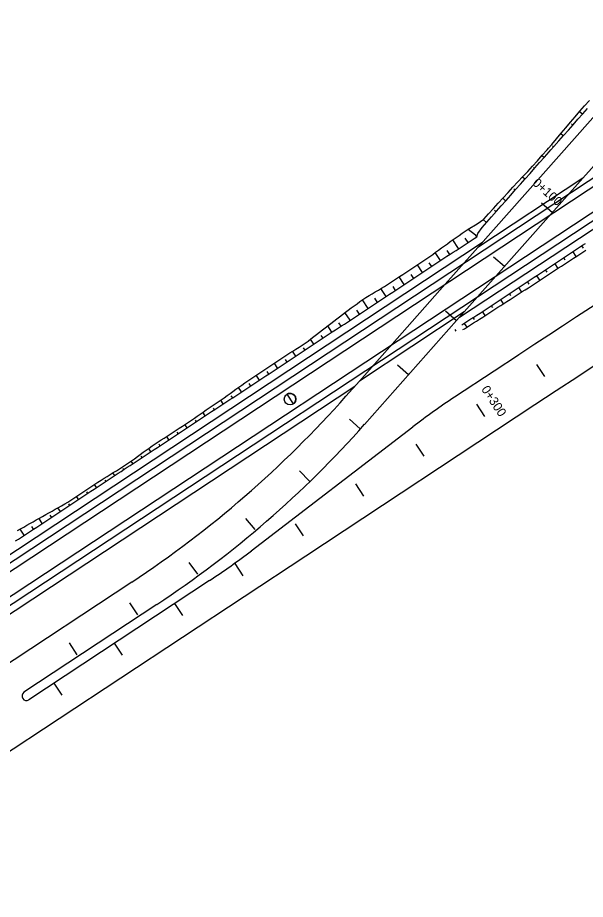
# Model space of a CAD drawing. Extents: x 6503541 to 6503743, y 5888004 to 5888145.
# Drawn here: x 6503598.537 to 6503600.423, y 5888050.855 to 5888053.781 of the extents above; entities that cross this region are included whole.
import ezdxf

# ---------------------------------------------------------------- set-up
doc = ezdxf.new("R2010")
doc.units = 0
doc.layers.add('12', color=7, linetype='Continuous')

msp = doc.modelspace()

# ---------------------------------------------------------------- linework, layer by layer
at = {"layer": '12'}
for p, q in [((6503592.6202, 5888048.0879), (6503601.3481, 5888053.842)), ((6503592.6334, 5888048.0679), (6503601.3614, 5888053.822)), ((6503592.6717, 5888048.0098), (6503601.3997, 5888053.7639)), ((6503592.6849, 5888047.9897), (6503601.4129, 5888053.7438)), ((6503600.0053, 5888052.7871), (6503601.4261, 5888053.7238)), ((6503600.6305, 5888053.6545), (6503600.0661, 5888053.0184)), ((6503600.414, 5888053.2477), (6503600.6975, 5888053.5672)), ((6503600.0206, 5888052.8044), (6503600.414, 5888053.2477)), ((6503600.0206, 5888052.8044), (6503600.414, 5888053.2477)), ((6503600.414, 5888053.2477), (6503600.0661, 5888053.0184)), ((6503600.414, 5888053.2477), (6503600.0661, 5888053.0184)), ((6503600.0621, 5888053.0539), (6503600.0584, 5888053.0602)), ((6503596.6916, 5888050.8008), (6503600.0814, 5888053.0357)), ((6503600.0019, 5888053.0143), (6503599.9827, 5888053.0435)), ((6503600.0221, 5888053.0492), (6503600.032, 5888053.0341)), ((6503599.9418, 5888052.9747), (6503599.9242, 5888053.0013)), ((6503599.9399, 5888052.8761), (6503600.0661, 5888053.0184)), ((6503599.9399, 5888052.8761), (6503600.0661, 5888053.0184)), ((6503599.9627, 5888053.0085), (6503599.9719, 5888052.9945)), ((6503600.381, 5888053.0038), (6503600.3915, 5888052.9879)), ((6503600.4163, 5888053.0156), (6503600.4111, 5888053.0236)), ((6503600.3562, 5888052.976), (6503600.351, 5888052.984)), ((6503599.8817, 5888052.935), (6503599.865, 5888052.9604)), ((6503599.9034, 5888052.9675), (6503599.9118, 5888052.9548)), ((6503600.296, 5888052.9365), (6503600.2909, 5888052.9443)), ((6503600.3209, 5888052.9641), (6503600.3313, 5888052.9484)), ((6503599.8216, 5888052.8954), (6503599.8047, 5888052.921)), ((6503599.8433, 5888052.928), (6503599.8517, 5888052.9152)), ((6503600.2608, 5888052.9245), (6503600.2711, 5888052.9089)), ((6503599.7831, 5888052.8884), (6503599.7915, 5888052.8756)), ((6503600.2007, 5888052.8849), (6503600.2105, 5888052.87)), ((6503600.2359, 5888052.8969), (6503600.2307, 5888052.9047)), ((6503599.6727, 5888052.5751), (6503599.9399, 5888052.8761)), ((6503599.6727, 5888052.5751), (6503599.9399, 5888052.8761)), ((6503599.7615, 5888052.8558), (6503599.7441, 5888052.8821)), ((6503600.1754, 5888052.8578), (6503600.1706, 5888052.8651)), ((6503599.7014, 5888052.8161), (6503599.6827, 5888052.8445)), ((6503599.7223, 5888052.8498), (6503599.7314, 5888052.8359)), ((6503600.1151, 5888052.8185), (6503600.1105, 5888052.8254)), ((6503600.1406, 5888052.8453), (6503600.15, 5888052.831)), ((6503599.6413, 5888052.7765), (6503599.6244, 5888052.8022)), ((6503599.6623, 5888052.8099), (6503599.6713, 5888052.7963)), ((6503600.0206, 5888052.8044), (6503599.6727, 5888052.5751)), ((6503600.0206, 5888052.8044), (6503599.6727, 5888052.5751)), ((6503599.6896, 5888052.4313), (6503600.0206, 5888052.8044)), ((6503600.0805, 5888052.8056), (6503600.0894, 5888052.792)), ((6503599.6035, 5888052.7684), (6503599.6112, 5888052.7567)), ((6503600.0203, 5888052.766), (6503600.0287, 5888052.7534)), ((6503600.0548, 5888052.7792), (6503600.0504, 5888052.7858)), ((6503599.5812, 5888052.7369), (6503599.5672, 5888052.7581)), ((6503599.994, 5888052.7405), (6503599.9903, 5888052.7462)), ((6503599.521, 5888052.6972), (6503599.51, 5888052.714)), ((6503599.5448, 5888052.7265), (6503599.5511, 5888052.7171)), ((6503599.4857, 5888052.6854), (6503599.491, 5888052.6774)), ((6503599.4609, 5888052.6576), (6503599.4504, 5888052.6736)), ((6503600.2004, 5888052.6611), (6503600.1195, 5888052.6078)), ((6503599.4008, 5888052.618), (6503599.3901, 5888052.6342)), ((6503599.4256, 5888052.6459), (6503599.4309, 5888052.6378)), ((6503599.3407, 5888052.5784), (6503599.3301, 5888052.5945)), ((6503599.3654, 5888052.6063), (6503599.3708, 5888052.5982)), ((6503600.1195, 5888052.6078), (6503599.9886, 5888052.5215)), ((6503599.3054, 5888052.5665), (6503599.3107, 5888052.5585)), ((6503599.6277, 5888052.5243), (6503599.6727, 5888052.5751)), ((6503596.8173, 5888050.6854), (6503599.6574, 5888052.5577)), ((6503599.2806, 5888052.5387), (6503599.2708, 5888052.5536)), ((6503599.2205, 5888052.4991), (6503599.212, 5888052.512)), ((6503599.246, 5888052.5258), (6503599.2505, 5888052.5189)), ((6503599.1864, 5888052.4854), (6503599.1904, 5888052.4793)), ((6503600.2545, 5888052.4955), (6503599.494, 5888051.9942)), ((6503599.1267, 5888052.4452), (6503599.1303, 5888052.4396)), ((6503599.1604, 5888052.4595), (6503599.1527, 5888052.4712)), ((6503599.1003, 5888052.4198), (6503599.0932, 5888052.4306)), ((6503599.3135, 5888052.0118), (6503599.8499, 5888052.4228)), ((6503599.0401, 5888052.3802), (6503599.0327, 5888052.3915)), ((6503599.0666, 5888052.4055), (6503599.0702, 5888052.4)), ((6503599.0063, 5888052.3662), (6503599.0101, 5888052.3604)), ((6503598.98, 5888052.3406), (6503598.9727, 5888052.3517)), ((6503598.9199, 5888052.3009), (6503598.9145, 5888052.3092)), ((6503598.9468, 5888052.3256), (6503598.95, 5888052.3208)), ((6503598.8598, 5888052.2613), (6503598.8538, 5888052.2704)), ((6503598.8872, 5888052.2852), (6503598.8899, 5888052.2811)), ((6503598.8265, 5888052.2465), (6503598.8298, 5888052.2415)), ((6503598.7997, 5888052.2217), (6503598.7928, 5888052.2322)), ((6503598.7396, 5888052.182), (6503598.7327, 5888052.1925)), ((6503598.7662, 5888052.2071), (6503598.7696, 5888052.2019)), ((6503598.6795, 5888052.1424), (6503598.6713, 5888052.1547)), ((6503598.7061, 5888052.1675), (6503598.7095, 5888052.1622)), ((6503598.6447, 5888052.1298), (6503598.6494, 5888052.1226)), ((6503598.6194, 5888052.1028), (6503598.6085, 5888052.1193)), ((6503598.5593, 5888052.0632), (6503598.5456, 5888052.0839)), ((6503598.5832, 5888052.0923), (6503598.5893, 5888052.083)), ((6503599.4945, 5888051.9945), (6503597.9384, 5888050.9686)), ((6503598.9165, 5888051.9081), (6503597.8024, 5888051.1736)), ((6503599.1748, 5888051.9131), (6503598.575, 5888051.5177)), ((6503598.9997, 5888051.8336), (6503598.5585, 5888051.5427))]:
    msp.add_line(p, q, dxfattribs=at)
for points in [[(6503600.0332, 5888053.079), (6503600.0634, 5888053.0964), (6503600.0853, 5888053.1115), (6503600.1013, 5888053.1294), (6503600.1173, 5888053.1472), (6503600.1334, 5888053.165), (6503600.1496, 5888053.1828), (6503600.1659, 5888053.2004), (6503600.1823, 5888053.2179), (6503600.1986, 5888053.2355), (6503600.215, 5888053.2531), (6503600.2314, 5888053.2706), (6503600.2477, 5888053.2882), (6503600.264, 5888053.3059), (6503600.2798, 5888053.3239), (6503600.2956, 5888053.342), (6503600.3009, 5888053.3481), (6503600.3112, 5888053.3602), (6503600.3268, 5888053.3785), (6503600.3423, 5888053.3968), (6503600.3579, 5888053.4151), (6503600.3734, 5888053.4334), (6503600.3889, 5888053.4517), (6503600.4044, 5888053.47), (6503600.4199, 5888053.4883), (6503600.436, 5888053.5062)], [(6503600.062, 5888053.0539), (6503600.0657, 5888053.0647), (6503600.0797, 5888053.0843), (6503600.0956, 5888053.1023), (6503600.1116, 5888053.1202), (6503600.1275, 5888053.1382), (6503600.1434, 5888053.1561), (6503600.1594, 5888053.1741), (6503600.1753, 5888053.192), (6503600.1912, 5888053.21), (6503600.2071, 5888053.2279), (6503600.2231, 5888053.2459), (6503600.239, 5888053.2639), (6503600.2549, 5888053.2818), (6503600.2709, 5888053.2998), (6503600.2868, 5888053.3177), (6503600.3027, 5888053.3357), (6503600.3081, 5888053.3418), (6503600.3186, 5888053.3536), (6503600.3346, 5888053.3716), (6503600.3505, 5888053.3895), (6503600.3664, 5888053.4075), (6503600.3824, 5888053.4254), (6503600.3983, 5888053.4434), (6503600.4142, 5888053.4613), (6503600.4301, 5888053.4793)], [(6503600.413, 5888053.46), (6503600.4032, 5888053.4686)], [(6503600.3811, 5888053.4241), (6503600.3767, 5888053.428)], [(6503600.3493, 5888053.3882), (6503600.3411, 5888053.3954)], [(6503600.3174, 5888053.3522), (6503600.3137, 5888053.3555)], [(6503600.2856, 5888053.3163), (6503600.2786, 5888053.3225)], [(6503600.2537, 5888053.2804), (6503600.2501, 5888053.2837)], [(6503600.2219, 5888053.2445), (6503600.2137, 5888053.2517)], [(6503600.19, 5888053.2086), (6503600.1855, 5888053.2126)], [(6503600.1581, 5888053.1727), (6503600.1483, 5888053.1814)], [(6503600.2772, 5888053.1658), (6503600.3131, 5888053.134)], [(6503600.1263, 5888053.1368), (6503600.1212, 5888053.1413)], [(6503600.0944, 5888053.1009), (6503600.0841, 5888053.1101)], [(6503598.5366, 5888052.0788), (6503598.5471, 5888052.0847), (6503598.5575, 5888052.0906), (6503598.568, 5888052.0965), (6503598.5785, 5888052.1024), (6503598.589, 5888052.1083), (6503598.5995, 5888052.1142), (6503598.6099, 5888052.1201), (6503598.6204, 5888052.126), (6503598.6309, 5888052.1319), (6503598.6414, 5888052.1378), (6503598.6518, 5888052.1438), (6503598.6623, 5888052.1497), (6503598.6728, 5888052.1556), (6503598.6833, 5888052.1615), (6503598.6938, 5888052.1674), (6503598.7041, 5888052.1736), (6503598.7141, 5888052.1802), (6503598.7241, 5888052.1868), (6503598.7341, 5888052.1934), (6503598.7441, 5888052.2), (6503598.7541, 5888052.2067), (6503598.7641, 5888052.2133), (6503598.7741, 5888052.2199), (6503598.7841, 5888052.2265), (6503598.7941, 5888052.2331), (6503598.8042, 5888052.2398), (6503598.8144, 5888052.2461), (6503598.8246, 5888052.2524), (6503598.8348, 5888052.2587), (6503598.845, 5888052.265), (6503598.8552, 5888052.2713), (6503598.8654, 5888052.2776), (6503598.8757, 5888052.2839), (6503598.8859, 5888052.2902), (6503598.8961, 5888052.2965), (6503598.9061, 5888052.3031), (6503598.9158, 5888052.3102), (6503598.9255, 5888052.3173), (6503598.9352, 5888052.3243), (6503598.9449, 5888052.3314), (6503598.9546, 5888052.3385), (6503598.9644, 5888052.3456), (6503598.9741, 5888052.3527), (6503598.9838, 5888052.3598), (6503598.9938, 5888052.3663), (6503599.0039, 5888052.3729), (6503599.0139, 5888052.3794), (6503599.024, 5888052.3859), (6503599.0341, 5888052.3924), (6503599.0442, 5888052.3989), (6503599.0543, 5888052.4054), (6503599.0643, 5888052.412), (6503599.0744, 5888052.4185), (6503599.0845, 5888052.425), (6503599.0946, 5888052.4315), (6503599.1046, 5888052.4381), (6503599.1145, 5888052.4449), (6503599.1244, 5888052.4517), (6503599.1342, 5888052.4585), (6503599.1441, 5888052.4653), (6503599.154, 5888052.4721), (6503599.1639, 5888052.4789), (6503599.1738, 5888052.4857), (6503599.1837, 5888052.4925), (6503599.1936, 5888052.4993), (6503599.2035, 5888052.5061), (6503599.2134, 5888052.5129), (6503599.2233, 5888052.5197), (6503599.2331, 5888052.5266), (6503599.2429, 5888052.5336), (6503599.2526, 5888052.5406), (6503599.2624, 5888052.5476), (6503599.2721, 5888052.5546), (6503599.2819, 5888052.5616), (6503599.2917, 5888052.5686), (6503599.3015, 5888052.5754), (6503599.3115, 5888052.5821), (6503599.3215, 5888052.5888), (6503599.3315, 5888052.5954), (6503599.3414, 5888052.6021), (6503599.3514, 5888052.6087), (6503599.3614, 5888052.6154), (6503599.3714, 5888052.622), (6503599.3815, 5888052.6286), (6503599.3915, 5888052.6351), (6503599.4015, 5888052.6417), (6503599.4116, 5888052.6483), (6503599.4216, 5888052.6548), (6503599.4317, 5888052.6614), (6503599.4417, 5888052.668), (6503599.4518, 5888052.6745), (6503599.4618, 5888052.6811), (6503599.4719, 5888052.6877), (6503599.4819, 5888052.6942), (6503599.4919, 5888052.7008), (6503599.5018, 5888052.7077), (6503599.5113, 5888052.715), (6503599.5209, 5888052.7224), (6503599.5304, 5888052.7297), (6503599.5399, 5888052.737), (6503599.5494, 5888052.7444), (6503599.559, 5888052.7517), (6503599.5685, 5888052.7591), (6503599.578, 5888052.7664), (6503599.5876, 5888052.7738), (6503599.5971, 5888052.7811), (6503599.6066, 5888052.7885), (6503599.6161, 5888052.7958), (6503599.6257, 5888052.8032), (6503599.6352, 5888052.8105), (6503599.645, 5888052.8175), (6503599.6547, 5888052.8245), (6503599.6645, 5888052.8315), (6503599.6743, 5888052.8385), (6503599.684, 5888052.8455), (6503599.694, 5888052.8521), (6503599.7043, 5888052.8583), (6503599.7146, 5888052.8645), (6503599.7249, 5888052.8706), (6503599.7353, 5888052.8768), (6503599.7456, 5888052.883), (6503599.7559, 5888052.8891), (6503599.7659, 5888052.8957), (6503599.776, 5888052.9022), (6503599.786, 5888052.9088), (6503599.7961, 5888052.9154), (6503599.8061, 5888052.9219), (6503599.8162, 5888052.9285), (6503599.8262, 5888052.9351), (6503599.8362, 5888052.9416), (6503599.8463, 5888052.9482), (6503599.8563, 5888052.9548), (6503599.8664, 5888052.9613), (6503599.8764, 5888052.9679), (6503599.8865, 5888052.9744), (6503599.8964, 5888052.9812), (6503599.9061, 5888052.9882), (6503599.9159, 5888052.9953), (6503599.9256, 5888053.0023), (6503599.9353, 5888053.0094), (6503599.9451, 5888053.0164), (6503599.9548, 5888053.0234), (6503599.9645, 5888053.0305), (6503599.9742, 5888053.0375), (6503599.9841, 5888053.0444), (6503599.9939, 5888053.0514), (6503600.0037, 5888053.0583), (6503600.0135, 5888053.0652), (6503600.0233, 5888053.0721), (6503600.0332, 5888053.079), (6503600.0584, 5888053.0602)], [(6503598.5306, 5888052.0443), (6503598.5406, 5888052.0509), (6503598.5506, 5888052.0575), (6503598.5606, 5888052.0641), (6503598.5707, 5888052.0707), (6503598.5807, 5888052.0773), (6503598.5907, 5888052.0839), (6503598.6007, 5888052.0905), (6503598.6107, 5888052.0971), (6503598.6208, 5888052.1037), (6503598.6308, 5888052.1103), (6503598.6408, 5888052.1169), (6503598.6508, 5888052.1235), (6503598.6608, 5888052.1301), (6503598.6708, 5888052.1367), (6503598.6809, 5888052.1433), (6503598.6909, 5888052.15), (6503598.7009, 5888052.1566), (6503598.7109, 5888052.1632), (6503598.7209, 5888052.1698), (6503598.731, 5888052.1764), (6503598.741, 5888052.183), (6503598.751, 5888052.1896), (6503598.761, 5888052.1962), (6503598.771, 5888052.2028), (6503598.781, 5888052.2094), (6503598.7911, 5888052.216), (6503598.8011, 5888052.2226), (6503598.8111, 5888052.2292), (6503598.8211, 5888052.2358), (6503598.8311, 5888052.2424), (6503598.8412, 5888052.249), (6503598.8512, 5888052.2556), (6503598.8612, 5888052.2622), (6503598.8712, 5888052.2688), (6503598.8812, 5888052.2754), (6503598.8913, 5888052.2821), (6503598.9013, 5888052.2887), (6503598.9113, 5888052.2953), (6503598.9213, 5888052.3019), (6503598.9313, 5888052.3085), (6503598.9413, 5888052.3151), (6503598.9514, 5888052.3217), (6503598.9614, 5888052.3283), (6503598.9714, 5888052.3349), (6503598.9814, 5888052.3415), (6503598.9914, 5888052.3481), (6503599.0015, 5888052.3547), (6503599.0115, 5888052.3613), (6503599.0215, 5888052.3679), (6503599.0315, 5888052.3745), (6503599.0415, 5888052.3811), (6503599.0516, 5888052.3877), (6503599.0616, 5888052.3943), (6503599.0716, 5888052.4009), (6503599.0816, 5888052.4075), (6503599.0916, 5888052.4142), (6503599.1016, 5888052.4208), (6503599.1117, 5888052.4274), (6503599.1217, 5888052.434), (6503599.1317, 5888052.4406), (6503599.1417, 5888052.4472), (6503599.1517, 5888052.4538), (6503599.1618, 5888052.4604), (6503599.1718, 5888052.467), (6503599.1818, 5888052.4736), (6503599.1918, 5888052.4802), (6503599.2018, 5888052.4868), (6503599.2119, 5888052.4934), (6503599.2219, 5888052.5), (6503599.2319, 5888052.5066), (6503599.2419, 5888052.5132), (6503599.2519, 5888052.5198), (6503599.2619, 5888052.5264), (6503599.272, 5888052.533), (6503599.282, 5888052.5396), (6503599.292, 5888052.5463), (6503599.302, 5888052.5529), (6503599.312, 5888052.5595), (6503599.3221, 5888052.5661), (6503599.3321, 5888052.5727), (6503599.3421, 5888052.5793), (6503599.3521, 5888052.5859), (6503599.3621, 5888052.5925), (6503599.3722, 5888052.5991), (6503599.3822, 5888052.6057), (6503599.3922, 5888052.6123), (6503599.4022, 5888052.6189), (6503599.4122, 5888052.6255), (6503599.4222, 5888052.6321), (6503599.4323, 5888052.6387), (6503599.4423, 5888052.6453), (6503599.4523, 5888052.6519), (6503599.4623, 5888052.6585), (6503599.4723, 5888052.6651), (6503599.4824, 5888052.6717), (6503599.4924, 5888052.6784), (6503599.5024, 5888052.685), (6503599.5124, 5888052.6916), (6503599.5224, 5888052.6982), (6503599.5324, 5888052.7048), (6503599.5425, 5888052.7114), (6503599.5525, 5888052.718), (6503599.5625, 5888052.7246), (6503599.5725, 5888052.7312), (6503599.5825, 5888052.7378), (6503599.5926, 5888052.7444), (6503599.6026, 5888052.751), (6503599.6126, 5888052.7576), (6503599.6226, 5888052.7642), (6503599.6326, 5888052.7708), (6503599.6427, 5888052.7774), (6503599.6527, 5888052.784), (6503599.6627, 5888052.7906), (6503599.6727, 5888052.7972), (6503599.6827, 5888052.8038), (6503599.6927, 5888052.8105), (6503599.7028, 5888052.8171), (6503599.7128, 5888052.8237), (6503599.7228, 5888052.8303), (6503599.7328, 5888052.8369), (6503599.7428, 5888052.8435), (6503599.7529, 5888052.8501), (6503599.7629, 5888052.8567), (6503599.7729, 5888052.8633), (6503599.7829, 5888052.8699), (6503599.7929, 5888052.8765), (6503599.803, 5888052.8831), (6503599.813, 5888052.8897), (6503599.823, 5888052.8963), (6503599.833, 5888052.9029), (6503599.843, 5888052.9095), (6503599.853, 5888052.9161), (6503599.8631, 5888052.9227), (6503599.8731, 5888052.9293), (6503599.8831, 5888052.9359), (6503599.8931, 5888052.9426), (6503599.9031, 5888052.9492), (6503599.9132, 5888052.9558), (6503599.9232, 5888052.9624), (6503599.9332, 5888052.969), (6503599.9432, 5888052.9756), (6503599.9532, 5888052.9822), (6503599.9633, 5888052.9888), (6503599.9733, 5888052.9954), (6503599.9833, 5888053.002), (6503599.9933, 5888053.0086), (6503600.0033, 5888053.0152), (6503600.0133, 5888053.0218), (6503600.0234, 5888053.0284), (6503600.0334, 5888053.035), (6503600.0434, 5888053.0416), (6503600.0534, 5888053.0482), (6503600.062, 5888053.0539)], [(6503600.0128, 5888052.761), (6503600.0228, 5888052.7676), (6503600.0328, 5888052.7742), (6503600.0429, 5888052.7808), (6503600.0529, 5888052.7874), (6503600.0629, 5888052.794), (6503600.0729, 5888052.8006), (6503600.0829, 5888052.8073), (6503600.093, 5888052.8139), (6503600.103, 5888052.8205), (6503600.113, 5888052.8271), (6503600.123, 5888052.8337), (6503600.133, 5888052.8403), (6503600.143, 5888052.8469), (6503600.1531, 5888052.8535), (6503600.1631, 5888052.8601), (6503600.1731, 5888052.8667), (6503600.1831, 5888052.8733), (6503600.1931, 5888052.8799), (6503600.2032, 5888052.8865), (6503600.2132, 5888052.8931), (6503600.2232, 5888052.8997), (6503600.2332, 5888052.9063), (6503600.2432, 5888052.9129), (6503600.2532, 5888052.9195), (6503600.2633, 5888052.9261), (6503600.2733, 5888052.9328), (6503600.2833, 5888052.9394), (6503600.2933, 5888052.946), (6503600.3033, 5888052.9526), (6503600.3134, 5888052.9592), (6503600.3234, 5888052.9658), (6503600.3334, 5888052.9724), (6503600.3434, 5888052.979), (6503600.3534, 5888052.9856), (6503600.3635, 5888052.9922), (6503600.3735, 5888052.9988), (6503600.3835, 5888053.0054), (6503600.3935, 5888053.012), (6503600.4035, 5888053.0186), (6503600.4135, 5888053.0252), (6503600.4236, 5888053.0318)], [(6503600.0157, 5888052.7457), (6503600.0209, 5888052.7487), (6503600.0312, 5888052.7549), (6503600.0415, 5888052.7611), (6503600.0516, 5888052.7676), (6503600.0616, 5888052.7741), (6503600.0717, 5888052.7806), (6503600.0818, 5888052.7871), (6503600.0919, 5888052.7936), (6503600.102, 5888052.8001), (6503600.1121, 5888052.8066), (6503600.1222, 5888052.8131), (6503600.1323, 5888052.8196), (6503600.1424, 5888052.8261), (6503600.1525, 5888052.8326), (6503600.1625, 5888052.8391), (6503600.1726, 5888052.8456), (6503600.1827, 5888052.8521), (6503600.1928, 5888052.8586), (6503600.2029, 5888052.8651), (6503600.213, 5888052.8716), (6503600.2232, 5888052.8779), (6503600.2334, 5888052.8842), (6503600.2436, 5888052.8906), (6503600.2535, 5888052.8973), (6503600.2635, 5888052.904), (6503600.2735, 5888052.9106), (6503600.2836, 5888052.9171), (6503600.2936, 5888052.9237), (6503600.3037, 5888052.9303), (6503600.3137, 5888052.9369), (6503600.3237, 5888052.9434), (6503600.3338, 5888052.95), (6503600.3438, 5888052.9566), (6503600.3538, 5888052.9632), (6503600.3639, 5888052.9698), (6503600.3739, 5888052.9763), (6503600.3839, 5888052.9829), (6503600.394, 5888052.9895), (6503600.404, 5888052.9961), (6503600.4141, 5888053.0026), (6503600.4241, 5888053.0092)], [(6503600.1538, 5888052.9545), (6503600.1179, 5888052.9863)], [(6503599.9945, 5888052.7749), (6503599.9586, 5888052.8068)], [(6503599.8352, 5888052.5954), (6503599.7993, 5888052.6273)], [(6503600.2884, 5888052.5897), (6503600.262, 5888052.6298)], [(6503599.4314, 5888052.531), (6503599.4526, 5888052.4989)], [(6503600.0616, 5888052.4977), (6503600.088, 5888052.4576)], [(6503599.6755, 5888052.4159), (6503599.64, 5888052.4482)], [(6503599.8876, 5888052.3255), (6503599.8612, 5888052.3656)], [(6503599.5068, 5888052.2429), (6503599.4736, 5888052.2776)], [(6503599.6872, 5888052.1934), (6503599.6608, 5888052.2335)], [(6503599.3265, 5888052.082), (6503599.2958, 5888052.1189)], [(6503599.4869, 5888052.0613), (6503599.4605, 5888052.1014)], [(6503599.1355, 5888051.934), (6503599.1075, 5888051.9729)], [(6503599.2865, 5888051.9292), (6503599.2601, 5888051.9693)], [(6503598.9361, 5888051.7988), (6503598.9096, 5888051.8389)], [(6503599.0861, 5888051.7971), (6503599.0597, 5888051.8372)], [(6503598.7357, 5888051.6667), (6503598.7093, 5888051.7068)], [(6503598.8858, 5888051.665), (6503598.8593, 5888051.7051)], [(6503598.6854, 5888051.5329), (6503598.659, 5888051.573)]]:
    msp.add_lwpolyline(points, dxfattribs=at)
msp.add_circle((6503599.442, 5888052.5149), 0.0192, dxfattribs=at)
for centre, radius, start, end in [((6503629.9308, 5888007.4817), 53.916, 117.58603, 123.39571), ((6503629.9308, 5888007.4817), 54.084, 119.63838, 123.39571), ((6503599.442, 5888052.5149), 0.0192, 358.9485, 123.3957), ((6503596.9349, 5888054.9137), 3.6, 303.3957, 318.417), ((6503599.442, 5888052.5149), 0.0192, 303.3957, 358.9485), ((6503601.3096, 5888050.5178), 2.4, 123.3957, 127.4622), ((6503597.0776, 5888054.749), 3.492, 303.3957, 318.417), ((6503597.8538, 5888053.9168), 2.4, 303.3957, 307.4622), ((6503598.5668, 5888051.5302), 0.015, 123.3957, 303.3957)]:
    msp.add_arc(centre, radius, start, end, dxfattribs=at)

# ---------------------------------------------------------------- texts
for s, rotation, p in [('0+100', 318.417, (6503600.2452, 5888053.2284)), ('0+300', 303.3957, (6503600.0758, 5888052.5476))]:
    msp.add_text(s, height=0.03, rotation=rotation, dxfattribs=at).set_placement(p)

doc.saveas('drawing.dxf')
